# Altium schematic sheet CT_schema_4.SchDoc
size 399 x 269 mm
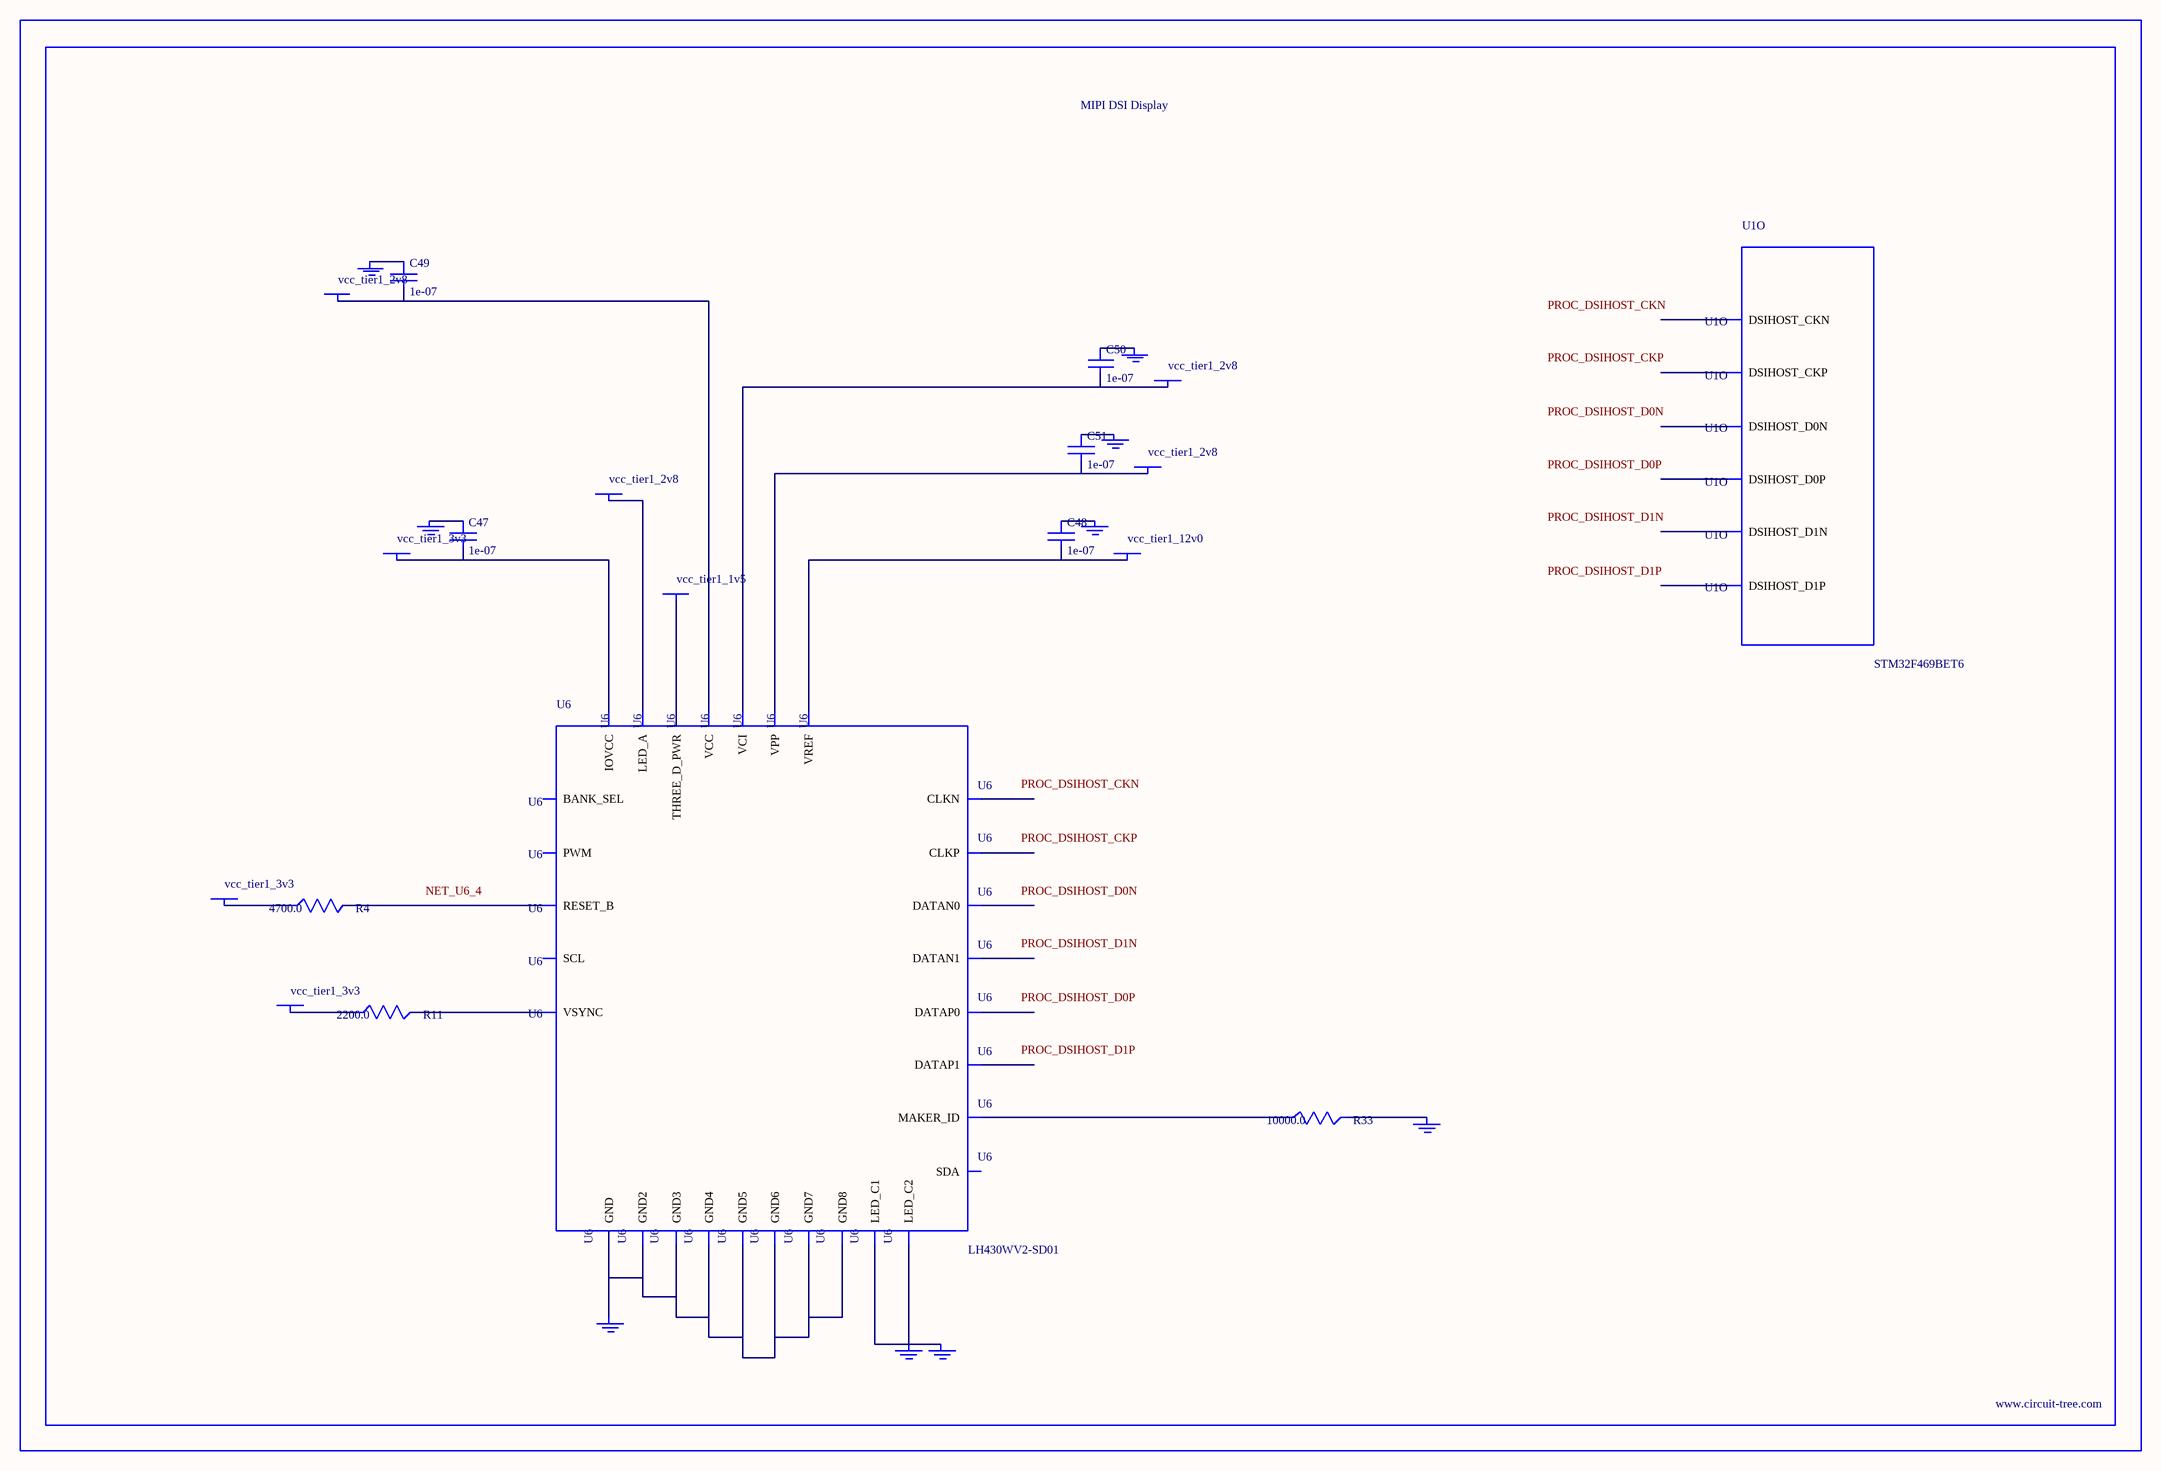
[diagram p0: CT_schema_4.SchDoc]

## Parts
BORDER3  (no value)
C47  1e-07  [C0402]
C48  1e-07  [C0402]
C49  1e-07  [C0402]
C50  1e-07  [C0402]
C51  1e-07  [C0402]
GND_INSTANCE_3_0  (no value)
GND_INSTANCE_3_1  (no value)
GND_INSTANCE_3_2  (no value)
GND_INSTANCE_3_3  (no value)
GND_INSTANCE_3_4  (no value)
GND_INSTANCE_3_5  (no value)
GND_INSTANCE_3_6  (no value)
GND_INSTANCE_3_7  (no value)
GND_INSTANCE_3_8  (no value)
POWER_INSTANCE_3_0  vcc_tier1_3v3
POWER_INSTANCE_3_1  vcc_tier1_2v8
POWER_INSTANCE_3_2  vcc_tier1_2v8
POWER_INSTANCE_3_3  vcc_tier1_2v8
POWER_INSTANCE_3_4  vcc_tier1_2v8
POWER_INSTANCE_3_5  vcc_tier1_12v0
POWER_INSTANCE_3_6  vcc_tier1_3v3
POWER_INSTANCE_3_7  vcc_tier1_3v3
POWER_INSTANCE_3_8  vcc_tier1_1v5
R4  4700.0  [R0603]
R11  2200.0  [R0603]
R33  10000.0  [R0603]
U1  STM32F469BET6  [LQFP208]  (part O of 18)
U6  LH430WV2-SD01  [LH430WV2-SD01]

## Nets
NetC47_1: C47.1 GND_INSTANCE_3_0.0(GND)
NetC47_2: C47.2 POWER_INSTANCE_3_0.0(PWR) U6.2(IOVCC)
NetC48_1: C48.1 GND_INSTANCE_3_7.0(GND)
NetC48_2: C48.2 POWER_INSTANCE_3_5.0(PWR) U6.30(VREF)
NetC49_1: C49.1 GND_INSTANCE_3_5.0(GND)
NetC49_2: C49.2 POWER_INSTANCE_3_3.0(PWR) U6.22(VCC)
NetC50_1: C50.1 GND_INSTANCE_3_4.0(GND)
NetC50_2: C50.2 POWER_INSTANCE_3_2.0(PWR) U6.21(VCI)
NetC51_1: C51.1 GND_INSTANCE_3_6.0(GND)
NetC51_2: C51.2 POWER_INSTANCE_3_4.0(PWR) U6.23(VPP)
NetGND_INSTANCE_3_1_0: GND_INSTANCE_3_1.0(GND) GND_INSTANCE_3_2.0(GND) U6.17(LED_C1) U6.18(LED_C2)
NetGND_INSTANCE_3_3_0: GND_INSTANCE_3_3.0(GND) R33.2
NetGND_INSTANCE_3_8_0: GND_INSTANCE_3_8.0(GND) U6.1(GND) U6.6(GND2) U6.9(GND3) U6.12(GND4) U6.15(GND5) U6.19(GND6) U6.24(GND7) U6.27(GND8)
NetPOWER_INSTANCE_3_1_0: POWER_INSTANCE_3_1.0(PWR) U6.16(LED_A)
NetPOWER_INSTANCE_3_6_0: POWER_INSTANCE_3_6.0(PWR) R4.1
NetPOWER_INSTANCE_3_7_0: POWER_INSTANCE_3_7.0(PWR) R11.1
NetPOWER_INSTANCE_3_8_0: POWER_INSTANCE_3_8.0(PWR) U6.29(THREE_D_PWR)
NetR4_2: R4.2 U6.4(RESET_B)
NetR11_2: R11.2 U6.5(VSYNC)
NetR33_1: R33.1 U6.20(MAKER_ID)

Not connected (* = marked no-connect by the designer): U1 120(DSIHOST_D0P) 121(DSIHOST_D0N) 123(DSIHOST_CKP) 124(DSIHOST_CKN) 126(DSIHOST_D1P) 127(DSIHOST_D1N); U6 3(PWM) 7(DATAN0) 8(DATAP0) 10(DATAN1) 11(DATAP1) 13(CLKN) 14(CLKP) 25(SCL) 26(SDA) 28(BANK_SEL)

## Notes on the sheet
- Labels drawn without touching a wire or pin: NET_U6_4, PROC_DSIHOST_CKN, PROC_DSIHOST_CKP, PROC_DSIHOST_D0N, PROC_DSIHOST_D0P, PROC_DSIHOST_D1N, PROC_DSIHOST_D1P

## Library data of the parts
BORDER3 = BORDER_PAGE3
C47-C51 = C0402C104K3RACTU
GND_INSTANCE_3_0-GND_INSTANCE_3_8 = GND
POWER_INSTANCE_3_0-POWER_INSTANCE_3_8 = PWR
R4 = RC0603JR-074K7L
R11 = RC0603JR-072K2L
R33 = RC0603JR-0710KL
